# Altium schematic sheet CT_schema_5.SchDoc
size 445 x 328 mm
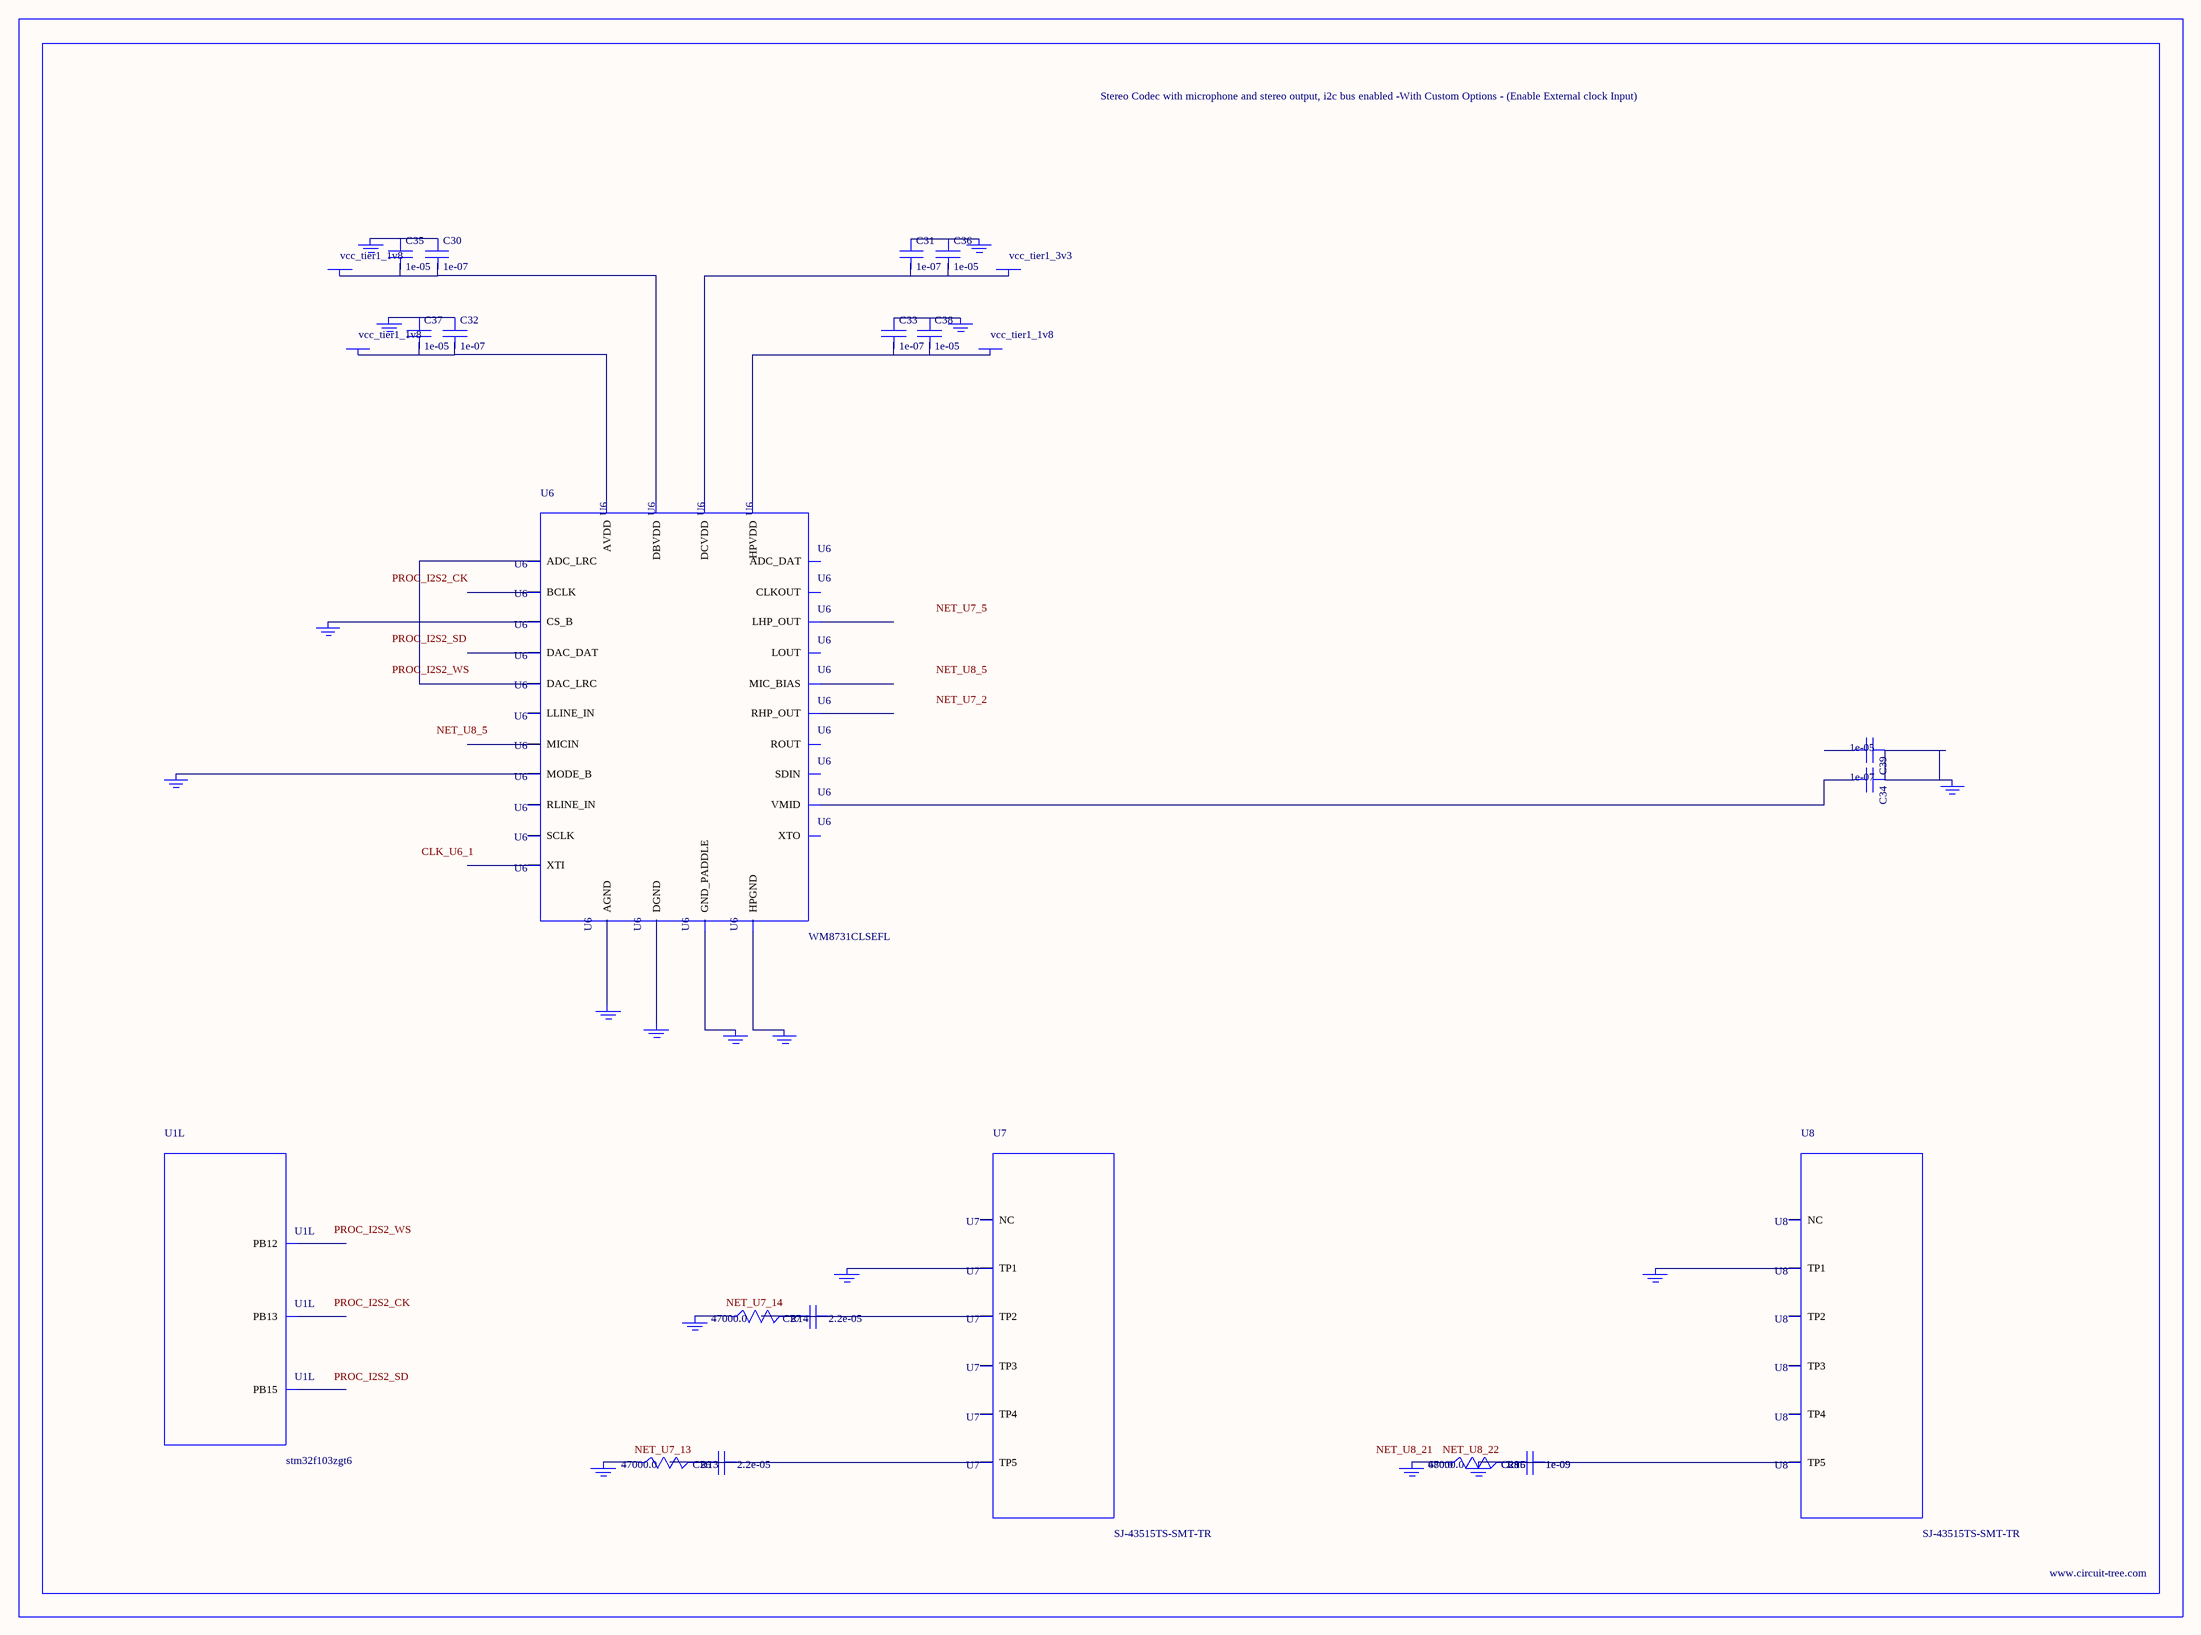
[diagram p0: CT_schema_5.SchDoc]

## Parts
BORDER4  (no value)
C26  2.2e-05  [C1210]
C27  2.2e-05  [C1210]
C28  1e-09  [C0402]
C29  1e-09  [C0402]
C30  1e-07  [C0402]
C31  1e-07  [C0402]
C32  1e-07  [C0402]
C33  1e-07  [C0402]
C34  1e-07  [C0402]
C35  1e-05  [C0805]
C36  1e-05  [C0805]
C37  1e-05  [C0805]
C38  1e-05  [C0805]
C39  1e-05  [C0805]
GND_INSTANCE_4_0  (no value)
GND_INSTANCE_4_1  (no value)
GND_INSTANCE_4_2  (no value)
GND_INSTANCE_4_3  (no value)
GND_INSTANCE_4_4  (no value)
GND_INSTANCE_4_5  (no value)
GND_INSTANCE_4_6  (no value)
GND_INSTANCE_4_7  (no value)
GND_INSTANCE_4_8  (no value)
GND_INSTANCE_4_9  (no value)
GND_INSTANCE_4_10  (no value)
GND_INSTANCE_4_11  (no value)
GND_INSTANCE_4_12  (no value)
GND_INSTANCE_4_13  (no value)
GND_INSTANCE_4_14  (no value)
GND_INSTANCE_4_15  (no value)
GND_INSTANCE_4_16  (no value)
POWER_INSTANCE_4_0  vcc_tier1_3v3
POWER_INSTANCE_4_1  vcc_tier1_1v8
POWER_INSTANCE_4_2  vcc_tier1_1v8
POWER_INSTANCE_4_3  vcc_tier1_1v8
R13  47000.0  [R0603]
R14  47000.0  [R0603]
R15  47000.0  [R0603]
R16  680.0  [R0603]
U1  stm32f103zgt6  [LQFP144]  (part L of 12)
U6  WM8731CLSEFL  [QFN-28]
U7  SJ-43515TS-SMT-TR  [SJ-43515TS-SMT-TR]
U8  SJ-43515TS-SMT-TR  [SJ-43515TS-SMT-TR]

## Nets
NetC26_1: C26.1 C26.2 R13.2 U7.5(TP5)
NetC27_1: C27.1 C27.2 R14.2 U7.2(TP2)
NetC28_1: C28.1 C28.2 C29.1 C29.2 GND_INSTANCE_4_16.0(GND) R15.2 R16.2 U8.5(TP5)
NetC30_1: C30.1 C35.1 GND_INSTANCE_4_1.0(GND)
NetC30_2: C30.2 C35.2 POWER_INSTANCE_4_1.0(PWR) U6.5(DBVDD)
NetC31_1: C31.1 C36.1 GND_INSTANCE_4_0.0(GND)
NetC31_2: C31.2 C36.2 POWER_INSTANCE_4_0.0(PWR) U6.3(DCVDD)
NetC32_1: C32.1 C37.1 GND_INSTANCE_4_4.0(GND)
NetC32_2: C32.2 C37.2 POWER_INSTANCE_4_3.0(PWR) U6.18(AVDD)
NetC33_1: C33.1 C38.1 GND_INSTANCE_4_2.0(GND)
NetC33_2: C33.2 C38.2 POWER_INSTANCE_4_2.0(PWR) U6.12(HPVDD)
NetC34_1: C34.1 C39.1 GND_INSTANCE_4_5.0(GND)
NetC34_2: C34.2 U6.20(VMID)
NetGND_INSTANCE_4_3_0: GND_INSTANCE_4_3.0(GND) U6.15(HPGND)
NetGND_INSTANCE_4_6_0: GND_INSTANCE_4_6.0(GND) U6.25(MODE_B)
NetGND_INSTANCE_4_7_0: GND_INSTANCE_4_7.0(GND) U6.26(CS_B)
NetGND_INSTANCE_4_8_0: GND_INSTANCE_4_8.0(GND) U6.29(GND_PADDLE)
NetGND_INSTANCE_4_9_0: GND_INSTANCE_4_9.0(GND) U6.4(DGND)
NetGND_INSTANCE_4_10_0: GND_INSTANCE_4_10.0(GND) U6.19(AGND)
NetGND_INSTANCE_4_11_0: GND_INSTANCE_4_11.0(GND) U7.1(TP1)
NetGND_INSTANCE_4_12_0: GND_INSTANCE_4_12.0(GND) R14.1
NetGND_INSTANCE_4_13_0: GND_INSTANCE_4_13.0(GND) R13.1
NetGND_INSTANCE_4_14_0: GND_INSTANCE_4_14.0(GND) U8.1(TP1)
NetGND_INSTANCE_4_15_0: GND_INSTANCE_4_15.0(GND) R15.1 R16.1
NetU6_9: U6.9(DAC_LRC) U6.11(ADC_LRC)

Not connected (* = marked no-connect by the designer): C39 2; U1 73(PB12) 74(PB13) 76(PB15); U6 1(XTI) 2(XTO) 6(CLKOUT) 7(BCLK) 8(DAC_DAT) 10(ADC_DAT) 13(LHP_OUT) 14(RHP_OUT) 16(LOUT) 17(ROUT) 21(MIC_BIAS) 22(MICIN) 23(RLINE_IN) 24(LLINE_IN) 27(SDIN) 28(SCLK); U7 3(TP3) 4(TP4) 6(NC); U8 2(TP2) 3(TP3) 4(TP4) 6(NC)

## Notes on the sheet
- Labels drawn without touching a wire or pin: CLK_U6_1, NET_U7_2, NET_U7_5, NET_U7_13, NET_U7_14, NET_U8_5, NET_U8_21, NET_U8_22, PROC_I2S2_CK, PROC_I2S2_SD, PROC_I2S2_WS

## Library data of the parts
BORDER4 = BORDER_PAGE4
C26 C27 = C1210C224K5RACTU
C28 C29 = C0402C102K3RAC
C30-C34 = C0402C104K3RACTU
C35-C39 = C0805C106K8RACTU
GND_INSTANCE_4_0-GND_INSTANCE_4_16 = GND
POWER_INSTANCE_4_0-POWER_INSTANCE_4_3 = PWR
R13-R15 = RC0603JR-0747KL
R16 = RC0603JR-07680RL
